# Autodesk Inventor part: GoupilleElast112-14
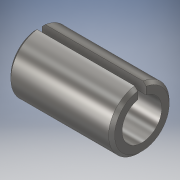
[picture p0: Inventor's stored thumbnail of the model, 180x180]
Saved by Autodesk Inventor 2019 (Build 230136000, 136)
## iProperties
Created: 1999-06
Part Number: GoupilleElast112-14
Material: Acier, carbone
Document SubType Name: Modeling
Designer: si-nd67
Density: 7.85 g/cm^3
Appearance: Semi-poli
Mass: 0.241396 g
Surface Area: 1.18899 cm^2
Volume: 0.0307511 cm^3
Sending System: SolidWorks 2014
Last Author: tjost
Last Saved: 2019-02-07
Author: si-nd67
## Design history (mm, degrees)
feature "Enlèv. mat.-Extru.2"
node "Solide1"
